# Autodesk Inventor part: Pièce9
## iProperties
Shininess: 64.0
Length Units: 11269
Angle Units: 11279
Time Units: 11290
Mass Units: 11283
Length Display Precision: 3
Angle Display Precision: 2
Compacted: True
Part Number: Pièce9
Document SubType Name: Modeling
Created: 2004-06
Material: Par défaut
Designer: laurent
Density: 0.0
Volumn: 0.0
Area: 0.0
PropertySet Name: Model Information
Control State: 0
Master: False
Checked Out: False
Author: laurent
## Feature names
1. Extrusion1
2. Balayage2
3. Balayage3
4. Révolution1 [Revolution]
5. Balayage4
6. Réseau rectangulaire1 [Rectangular Pattern]
7. Extrusion2
8. Extrusion3
